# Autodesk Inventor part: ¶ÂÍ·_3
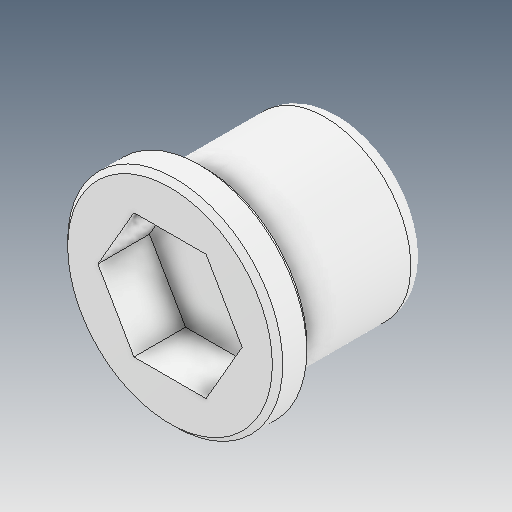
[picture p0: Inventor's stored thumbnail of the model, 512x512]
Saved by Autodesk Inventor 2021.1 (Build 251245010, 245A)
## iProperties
Created: 2021-06
Part Number: ¶ÂÍ·_3
Material: Ogólny
Document SubType Name: Modeling
Designer: user
Density: 1 g/cm^3
Appearance: Domyślna
Author: user
Revision Number: ÈÎºÎ
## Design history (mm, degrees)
feature "ÊäÈë1"
node "Bryła1"
